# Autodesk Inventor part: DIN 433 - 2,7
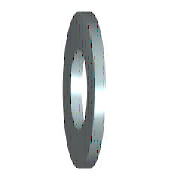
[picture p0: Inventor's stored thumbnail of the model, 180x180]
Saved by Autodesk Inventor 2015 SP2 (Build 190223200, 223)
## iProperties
Created: 2014-02
Part Number: DIN 433 - 2,7
Material: Stahl, weich
Description: Unterlegscheibe
Document SubType Name: Modeling
Standard: DIN 433
Designer: rYan
Standards Organization: DIN
Language: de-DE
Size Designation: 2,7
Categories: <MemberInstance><Categories><Category DisplayName="Verbindungselemente" InternalName="e4da775c-781d-43d5-af7c-5136215cf5a6" Mnemonic="FSTN"><Category DisplayNam
Density: 7.85 g/cm^3
Appearance: Halbpoliert
IsCustomPart: 0
Author: rYan
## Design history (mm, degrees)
sketch "Skizze"
  geometry: C1 r 2.5 at (0, 0); C2 r 1.35 at (0, 0); 1 further point
  constraints: 2 centre point, 2 coincident
  dimensions: "d0" = 2.7 diameter of C2 (= SD1); "d1" = 5 diameter of C1 (= SD2)
extrude "Körper" new body sketch "Skizze" distance "d2" = 0.5 (= SD); taper "d3" = 0 deg
workaxis "Work Axis1"
workplane "Work Plane1"
body "Solid1"
other parameters: "SD1" = 2.7 [user parameter; used in 1 equation term], "SD2" = 5 [user parameter; used in 1 equation term], "SD" = 0.5 [user parameter; used in 1 equation term], "d4" = 0, "d5" = 0, "d6" = 0, "d7" = 0, "NND" = 2.5 [user parameter]
